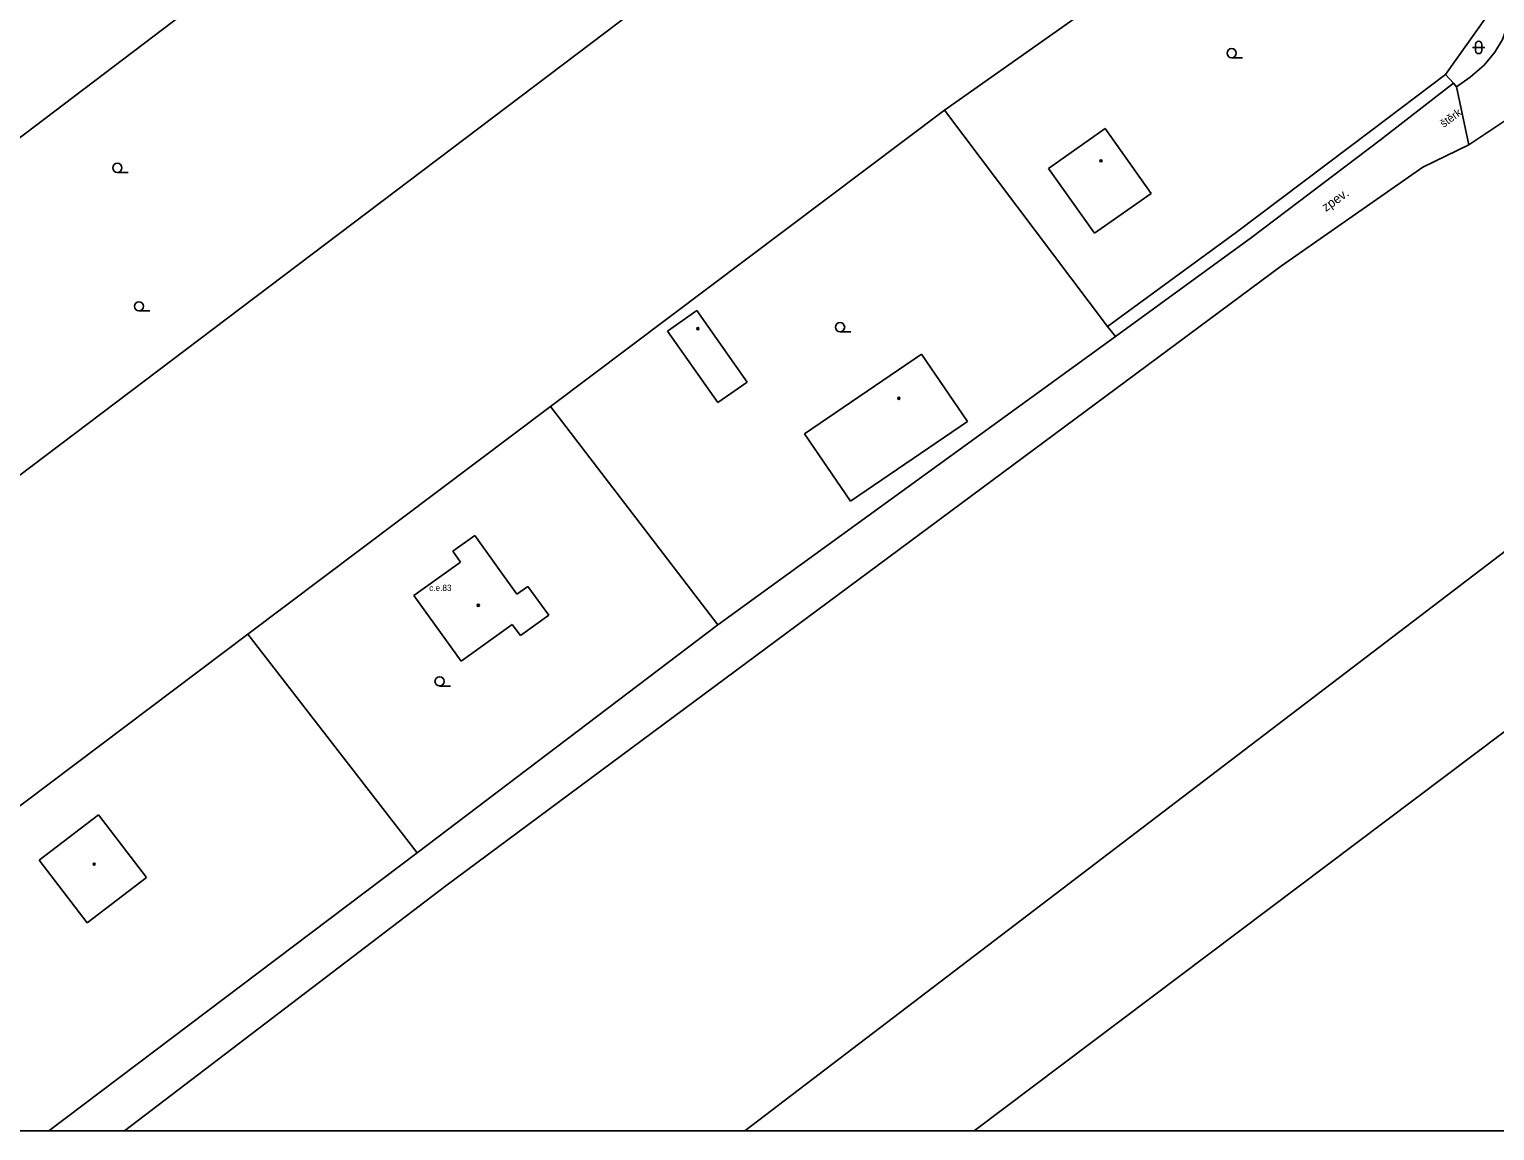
# Model space of a CAD drawing. Extents: x -594386 to -594050, y -1167541 to -1167175.
# Drawn here: x -594259.8 to -594140.8, y -1167540.8 to -1167451.4 of the extents above; entities that cross this region are included whole.
import ezdxf

# ---------------------------------------------------------------- set-up
doc = ezdxf.new("R2010")
doc.units = 0
for name, color, linetype in [('Level 36', 7, 'Continuous'), ('Level 39', 7, 'Continuous'), ('Vrstva 10', 7, 'Continuous'), ('Vrstva 11', 7, 'Continuous'), ('Vrstva 40', 7, 'Continuous'), ('Vrstva 42', 7, 'Continuous'), ('Vrstva 46', 7, 'Continuous'), ('Vrstva 51', 7, 'Continuous'), ('Vrstva 52', 7, 'Continuous'), ('Vrstva 63', 7, 'Continuous'), ('Vrstva 7', 7, 'Continuous')]:
    doc.layers.add(name, color=color, linetype=linetype)

msp = doc.modelspace()

# ---------------------------------------------------------------- linework, layer by layer
at = {"layer": 'Level 36'}
for p, q in [((-594142.61, -1167452.87), (-594141.61, -1167452.87)), ((-594142.36, -1167452.62), (-594142.36, -1167453.12)), ((-594141.86, -1167452.62), (-594141.86, -1167453.12)), ((-594162.17, -1167453.7), (-594161.3, -1167453.7)), ((-594252.66, -1167463.02), (-594251.78, -1167463.02)), ((-594250.9, -1167474.25), (-594250.02, -1167474.25)), ((-594193.97, -1167475.95), (-594193.09, -1167475.95)), ((-594226.49, -1167504.7), (-594225.61, -1167504.7))]:
    msp.add_line(p, q, dxfattribs=at)
for centre in [(-594162.17, -1167453.33), (-594252.66, -1167462.64), (-594250.9, -1167473.88), (-594193.97, -1167475.57), (-594226.49, -1167504.32)]:
    msp.add_circle(centre, 0.375, dxfattribs=at)
for centre, start, end in [((-594142.11, -1167452.62), 0, 180), ((-594142.11, -1167453.12), 180, 0)]:
    msp.add_arc(centre, 0.25, start, end, dxfattribs=at)
at = {"layer": 'Level 39'}
for centre, radius in [((-594172.78, -1167462.07), 0.09), ((-594172.78, -1167462.07), 0.0398), ((-594205.52, -1167475.7), 0.09), ((-594205.52, -1167475.7), 0.0398), ((-594189.2, -1167481.34), 0.09), ((-594189.2, -1167481.34), 0.0398), ((-594223.35, -1167498.15), 0.09), ((-594223.35, -1167498.15), 0.0398), ((-594254.54, -1167519.16), 0.09), ((-594254.54, -1167519.16), 0.0398)]:
    msp.add_circle(centre, radius, dxfattribs=at)
at = {"layer": 'Vrstva 10'}
for points in [[(-594139.7, -1167450.87), (-594140.18, -1167452.21), (-594140.81, -1167453.25), (-594141.67, -1167454.31), (-594142.79, -1167455.28), (-594143.9, -1167456.06)], [(-594142.9, -1167460.77), (-594137.62, -1167457.25), (-594136.57, -1167456.9), (-594135.11, -1167456.68)]]:
    msp.add_lwpolyline(points, dxfattribs=at)
at = {"layer": 'Vrstva 11'}
for points in [[(-594144.16, -1167455.77), (-594150.07, -1167460.37)], [(-594144.81, -1167455.06), (-594144.16, -1167455.77)], [(-594144.16, -1167455.77), (-594143.9, -1167456.06)], [(-594143.9, -1167456.06), (-594142.9, -1167460.77)], [(-594160.56, -1167468.3), (-594150.07, -1167460.37)], [(-594158.13, -1167470.6), (-594146.64, -1167462.59), (-594142.9, -1167460.77)], [(-594161.77, -1167467.87), (-594172.24, -1167475.51)], [(-594183.07, -1167540.79), (-594125.81, -1167497.69), (-594132.1, -1167487.77), (-594201.7, -1167540.79)]]:
    msp.add_lwpolyline(points, dxfattribs=at)
at = {"layer": 'Vrstva 51'}
for p, q in [((-594258.21, -1167540.79), (-594228.32, -1167518.23)), ((-594225.98, -1167520.92), (-594252.09, -1167540.79))]:
    msp.add_line(p, q, dxfattribs=at)
for points in [[(-594183.77, -1167401.96), (-594314.13, -1167500.77)], [(-594177.93, -1167425.11), (-594300.42, -1167517.66)], [(-594158.36, -1167438.82), (-594185.49, -1167457.95)], [(-594185.49, -1167457.95), (-594217.48, -1167482.01)], [(-594172.24, -1167475.51), (-594185.49, -1167457.95)], [(-594171.61, -1167476.34), (-594160.56, -1167468.3)], [(-594158.13, -1167470.6), (-594225.98, -1167520.92)], [(-594171.61, -1167476.34), (-594172.24, -1167475.51)], [(-594203.89, -1167499.73), (-594171.61, -1167476.34)], [(-594217.48, -1167482.01), (-594242.05, -1167500.49)], [(-594217.48, -1167482.01), (-594203.89, -1167499.73)], [(-594228.32, -1167518.23), (-594203.89, -1167499.73)], [(-594242.05, -1167500.49), (-594288.19, -1167535.19)], [(-594228.32, -1167518.23), (-594242.05, -1167500.49)]]:
    msp.add_lwpolyline(points, dxfattribs=at)
at = {"layer": 'Vrstva 52'}
for points in [[(-594177.03, -1167462.69), (-594172.43, -1167459.44)], [(-594172.43, -1167459.44), (-594168.71, -1167464.71)], [(-594173.31, -1167467.95), (-594177.03, -1167462.69)], [(-594168.71, -1167464.71), (-594173.31, -1167467.95)], [(-594207.97, -1167475.91), (-594205.59, -1167474.23)], [(-594205.59, -1167474.23), (-594201.52, -1167480.03)], [(-594203.9, -1167481.7), (-594207.97, -1167475.91)], [(-594196.85, -1167484.23), (-594187.37, -1167477.75)], [(-594187.37, -1167477.75), (-594183.63, -1167483.22)], [(-594201.52, -1167480.03), (-594203.9, -1167481.7)], [(-594183.63, -1167483.22), (-594193.12, -1167489.7)], [(-594193.12, -1167489.7), (-594196.85, -1167484.23)], [(-594225.42, -1167493.76), (-594223.64, -1167492.48)], [(-594223.64, -1167492.48), (-594220.22, -1167497.25)], [(-594224.78, -1167494.64), (-594225.42, -1167493.76)], [(-594228.57, -1167497.36), (-594224.78, -1167494.64)], [(-594224.74, -1167502.68), (-594228.57, -1167497.36)], [(-594220.22, -1167497.25), (-594219.33, -1167496.61)], [(-594219.33, -1167496.61), (-594217.63, -1167498.96)], [(-594220.59, -1167499.7), (-594224.74, -1167502.68)], [(-594219.93, -1167500.61), (-594220.59, -1167499.7)], [(-594217.63, -1167498.96), (-594219.93, -1167500.61)], [(-594259, -1167518.84), (-594254.19, -1167515.15)], [(-594254.19, -1167515.15), (-594250.29, -1167520.24)], [(-594255.1, -1167523.93), (-594259, -1167518.84)], [(-594250.29, -1167520.24), (-594255.1, -1167523.93)]]:
    msp.add_lwpolyline(points, dxfattribs=at)
at = {"layer": 'Vrstva 63'}
msp.add_lwpolyline([(-594386.36, -1167175.43), (-594049.75, -1167175.43), (-594049.75, -1167540.79), (-594386.36, -1167540.79)], close=True, dxfattribs=at)
at = {"layer": 'Vrstva 7'}
for points in [[(-594154.47, -1167435.37), (-594141.48, -1167450.37), (-594144.81, -1167455.06)], [(-594150.9, -1167459.66), (-594144.81, -1167455.06)], [(-594161.77, -1167467.87), (-594150.9, -1167459.66)]]:
    msp.add_lwpolyline(points, dxfattribs=at)

# ---------------------------------------------------------------- texts
at = {"layer": 'Vrstva 40'}
msp.add_text('štěrk', height=0.65, rotation=36.29, dxfattribs=at).set_placement((-594144.95, -1167459.4))
at = {"layer": 'Vrstva 42'}
msp.add_text('zpev.', height=0.75, rotation=35.3743, dxfattribs=at).set_placement((-594154.52, -1167466.23))
at = {"layer": 'Vrstva 46'}
msp.add_text('c.e.83', height=0.5, dxfattribs=at).set_placement((-594227.34, -1167496.98))

doc.saveas('drawing.dxf')
